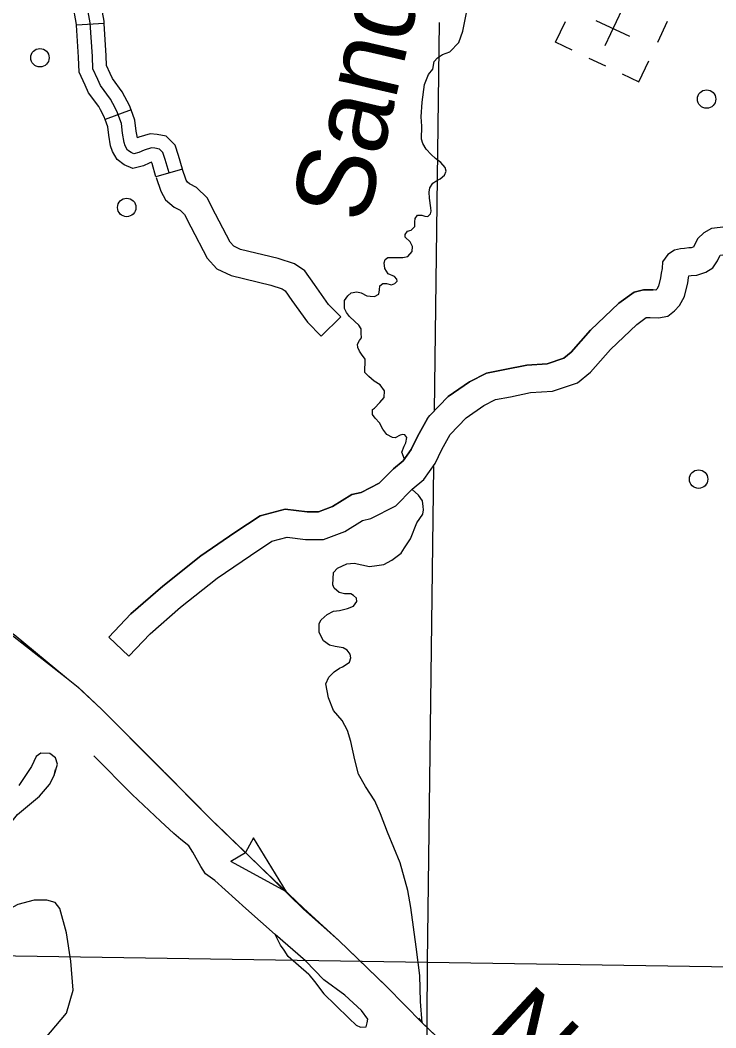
# Model space of a CAD drawing. Extents: x 1369979 to 1371646, y 379997 to 381064.
# Drawn here: x 1370948.5 to 1370992.7, y 380350.9 to 380415 of the extents above; entities that cross this region are included whole.
import ezdxf

# ---------------------------------------------------------------- set-up
doc = ezdxf.new("R2010")
doc.units = 0
doc.layers.add('R_Border Notes', color=7, linetype='Continuous')

msp = doc.modelspace()

# ---------------------------------------------------------------- linework, layer by layer
at = {"layer": 'R_Border Notes'}
for p, q in [((1370985.675, 380413.417), (1370987.683, 380417.652)), ((1370987.236, 380413.974), (1370985.108, 380414.982)), ((1370989.017, 380413.627), (1370989.644, 380414.951)), ((1370953.816, 380414.816), (1370952.061, 380414.709)), ((1370984.637, 380412.612), (1370985.696, 380412.11)), ((1370955.522, 380409.314), (1370953.875, 380408.7)), ((1370958.787, 380405.545), (1370957.096, 380405.067)), ((1370988.514, 380396.121), (1370988.535, 380396.122)), ((1370974.38, 380389.699), (1370974.518, 380389.882)), ((1370963.322, 380363.035), (1370962.804, 380362.099)), ((1370965.404, 380359.597), (1370963.315, 380363.034)), ((1370961.878, 380361.536), (1370962.795, 380362.088)), ((1370965.404, 380359.597), (1370961.877, 380361.529)), ((1370974.037, 380351.265), (1370978.237, 380347.272))]:
    msp.add_line(p, q, dxfattribs=at)
for points in [[(1370952.061, 380414.709), (1370952.059, 380414.749), (1370951.819, 380416.055), (1370951.819, 380417.029), (1370951.903, 380417.259), (1370952.08, 380417.772), (1370952.493, 380418.278), (1370953.065, 380418.69), (1370954.03, 380419.193), (1370954.825, 380419.643), (1370954.855, 380419.675), (1370954.867, 380419.705)], [(1370953.816, 380414.816), (1370953.807, 380414.962), (1370953.577, 380416.215), (1370953.577, 380416.722), (1370953.639, 380416.903), (1370953.707, 380416.986), (1370953.99, 380417.189), (1370954.87, 380417.649), (1370955.92, 380418.243), (1370956.371, 380418.719), (1370956.507, 380419.074)], [(1370954.362, 380409.725), (1370954.211, 380409.999), (1370953.585, 380410.86), (1370953.402, 380411.252), (1370953.089, 380411.931), (1370953.063, 380412.714), (1370952.933, 380414.856), (1370952.698, 380416.135), (1370952.698, 380416.874), (1370952.731, 380416.966)], [(1370973.965, 380408.871), (1370974.038, 380409.818), (1370974.189, 380410.94), (1370974.447, 380411.576), (1370974.719, 380411.91), (1370974.81, 380412.395), (1370975.007, 380412.622), (1370975.325, 380412.834), (1370975.795, 380413.016), (1370976.37, 380413.607), (1370976.627, 380414.32), (1370976.93, 380415.805)], [(1370975.118, 380414.871), (1370974.807, 380390.178)], [(1370983.584, 380413.111), (1370982.525, 380413.613), (1370983.153, 380414.937)], [(1370953.875, 380408.7), (1370953.809, 380408.878), (1370953.586, 380409.312), (1370953.468, 380409.526), (1370952.824, 380410.412), (1370952.605, 380410.882), (1370952.217, 380411.724), (1370952.185, 380412.673), (1370952.061, 380414.709)], [(1370955.522, 380409.314), (1370955.42, 380409.589), (1370955.138, 380410.138), (1370954.954, 380410.471), (1370954.346, 380411.309), (1370954.2, 380411.622), (1370953.962, 380412.138), (1370953.941, 380412.756), (1370953.816, 380414.816)], [(1370986.761, 380411.605), (1370987.82, 380411.103), (1370988.447, 380412.426)], [(1370957.941, 380405.306), (1370957.701, 380406.157), (1370957.554, 380406.598), (1370957.327, 380406.826), (1370957.046, 380406.879), (1370956.819, 380406.906), (1370956.351, 380406.759), (1370956.017, 380406.598), (1370955.71, 380406.518), (1370955.523, 380406.598), (1370955.309, 380406.759), (1370955.149, 380407.026), (1370955.082, 380407.24), (1370954.988, 380407.829), (1370954.908, 380408.444), (1370954.614, 380409.233), (1370954.362, 380409.725)], [(1370958.787, 380405.545), (1370958.541, 380406.415), (1370958.322, 380407.073), (1370957.757, 380407.638), (1370957.18, 380407.748), (1370956.735, 380407.801), (1370956.027, 380407.578), (1370955.926, 380407.53), (1370955.858, 380407.955), (1370955.767, 380408.657), (1370955.522, 380409.314)], [(1370957.096, 380405.067), (1370956.861, 380405.899), (1370956.831, 380405.988), (1370956.675, 380405.939), (1370956.321, 380405.769), (1370955.64, 380405.592), (1370955.079, 380405.832), (1370954.644, 380406.159), (1370954.341, 380406.664), (1370954.224, 380407.039), (1370954.118, 380407.703), (1370954.05, 380408.231), (1370953.875, 380408.7)], [(1370974.586, 380403.091), (1370974.511, 380403.702), (1370974.48, 380404.081), (1370974.526, 380404.369), (1370974.723, 380404.657), (1370974.904, 380404.778), (1370975.177, 380404.93), (1370975.449, 380405.172), (1370975.555, 380405.43), (1370975.51, 380405.657), (1370975.222, 380405.961), (1370974.889, 380406.218), (1370974.617, 380406.476), (1370974.283, 380406.825), (1370974.071, 380407.173), (1370973.996, 380407.446), (1370974.026, 380408.28), (1370973.965, 380408.871)], [(1370967.624, 380394.919), (1370968.868, 380396.161), (1370968.086, 380396.943), (1370967.189, 380398.216), (1370966.576, 380399.075), (1370965.925, 380399.522), (1370964.886, 380399.859), (1370962.485, 380400.447), (1370962.051, 380400.648), (1370961.826, 380400.901), (1370960.886, 380402.683), (1370960.356, 380403.715), (1370959.688, 380404.383), (1370959.238, 380404.609), (1370959.106, 380404.72), (1370959.034, 380404.854), (1370958.77, 380405.6)], [(1370957.113, 380405.013), (1370957.422, 380404.14), (1370957.716, 380403.594), (1370958.262, 380403.131), (1370958.646, 380402.939), (1370958.918, 380402.667), (1370959.327, 380401.871), (1370960.37, 380399.893), (1370960.98, 380399.206), (1370961.902, 380398.78), (1370964.405, 380398.167), (1370965.14, 380397.929), (1370965.324, 380397.802), (1370965.755, 380397.199), (1370966.736, 380395.808), (1370967.624, 380394.919)], [(1370969.42, 380396.173), (1370969.226, 380396.437), (1370969.105, 380396.68), (1370969.089, 380396.953), (1370969.105, 380397.195), (1370969.317, 380397.498), (1370969.529, 380397.68), (1370969.877, 380397.756), (1370970.165, 380397.68), (1370970.513, 380397.498), (1370970.74, 380397.468), (1370970.997, 380397.453), (1370971.285, 380397.604), (1370971.331, 380397.877), (1370971.346, 380398.12), (1370971.527, 380398.286), (1370971.77, 380398.286), (1370972.088, 380398.195), (1370972.3, 380398.271), (1370972.451, 380398.423), (1370972.436, 380398.544), (1370972.269, 380398.726), (1370971.876, 380398.893), (1370971.664, 380399.226), (1370971.618, 380399.59), (1370971.694, 380399.802), (1370971.861, 380399.923), (1370972.239, 380399.939), (1370972.799, 380399.923), (1370973.133, 380399.984), (1370973.405, 380400.317), (1370973.42, 380400.621), (1370973.269, 380400.924), (1370972.966, 380401.227), (1370972.951, 380401.394), (1370973.102, 380401.606), (1370973.329, 380401.666), (1370973.572, 380401.909), (1370973.572, 380402.197), (1370973.602, 380402.409), (1370973.738, 380402.621), (1370974.026, 380402.621), (1370974.208, 380402.561), (1370974.405, 380402.546), (1370974.571, 380402.697), (1370974.617, 380402.879), (1370974.586, 380403.091)], [(1370993.355, 380401.889), (1370992.428, 380401.769), (1370991.947, 380401.502), (1370991.565, 380401.147), (1370991.401, 380400.817), (1370991.291, 380400.598), (1370991.284, 380400.588), (1370991.204, 380400.564), (1370991.155, 380400.546), (1370990.991, 380400.538), (1370990.731, 380400.508), (1370990.476, 380400.476), (1370990.088, 380400.392), (1370989.669, 380400.113), (1370989.321, 380399.665), (1370989.295, 380399.229), (1370989.235, 380398.939), (1370989.197, 380398.647), (1370989.064, 380398.105), (1370988.956, 380397.915), (1370988.907, 380397.86), (1370988.728, 380397.871)], [(1370988.535, 380396.122), (1370989.062, 380396.089), (1370989.662, 380396.204), (1370990.08, 380396.533), (1370990.393, 380396.887), (1370990.713, 380397.447), (1370990.927, 380398.323), (1370990.969, 380398.646), (1370990.995, 380398.769), (1370991.138, 380398.785), (1370991.508, 380398.804), (1370991.753, 380398.893), (1370992.075, 380398.988), (1370992.523, 380399.276), (1370992.815, 380399.715), (1370992.973, 380400.031), (1370992.992, 380400.07), (1370993.504, 380400.136), (1370994.074, 380400.159), (1370994.375, 380400.131), (1370995.218, 380399.916), (1370996.456, 380399.805)], [(1370988.535, 380396.122), (1370989.062, 380396.089), (1370989.662, 380396.204), (1370990.08, 380396.533), (1370990.393, 380396.887), (1370990.713, 380397.447), (1370990.927, 380398.323), (1370990.969, 380398.646), (1370990.995, 380398.769), (1370991.138, 380398.785), (1370991.508, 380398.804), (1370991.753, 380398.893), (1370992.075, 380398.988), (1370992.523, 380399.276), (1370992.815, 380399.715), (1370992.973, 380400.031), (1370992.992, 380400.07), (1370993.504, 380400.136), (1370994.074, 380400.159), (1370994.375, 380400.131), (1370995.218, 380399.916), (1370996.456, 380399.805)], [(1370974.518, 380389.882), (1370975.698, 380391.092), (1370977.048, 380392.032), (1370978.119, 380392.568), (1370979.304, 380392.805), (1370980.699, 380393.084), (1370981.978, 380393.161), (1370983.047, 380393.525), (1370983.512, 380393.913), (1370984.749, 380395.309), (1370986.555, 380397.034), (1370987.516, 380397.73), (1370988.107, 380397.878), (1370988.728, 380397.871)], [(1370988.728, 380397.871), (1370988.107, 380397.878), (1370987.516, 380397.73), (1370986.555, 380397.034), (1370984.749, 380395.309), (1370983.512, 380393.913), (1370983.047, 380393.525), (1370981.978, 380393.161), (1370980.699, 380393.084), (1370979.304, 380392.805), (1370978.119, 380392.568), (1370977.048, 380392.032), (1370975.698, 380391.092), (1370974.518, 380389.882)], [(1370970.888, 380390.271), (1370971.01, 380390.353), (1370971.343, 380390.717), (1370971.615, 380391.035), (1370971.646, 380391.46), (1370971.373, 380391.838), (1370970.994, 380392.066), (1370970.994, 380392.066), (1370970.646, 380392.354), (1370970.389, 380392.627), (1370970.389, 380392.884), (1370970.419, 380393.172), (1370970.419, 380393.475), (1370970.177, 380393.794), (1370970.056, 380393.976), (1370969.95, 380394.203), (1370969.934, 380394.415), (1370970.056, 380394.643), (1370970.177, 380394.824), (1370970.162, 380395.128), (1370970.162, 380395.385), (1370970.01, 380395.628), (1370969.753, 380395.855), (1370969.42, 380396.173)], [(1370975.815, 380388.678), (1370976.84, 380389.745), (1370977.949, 380390.517), (1370978.695, 380390.891), (1370979.649, 380391.081), (1370980.926, 380391.337), (1370982.32, 380391.421), (1370983.922, 380391.966), (1370984.74, 380392.648), (1370986.016, 380394.088), (1370987.683, 380395.68), (1370988.273, 380396.108), (1370988.323, 380396.12), (1370988.51, 380396.12), (1370988.514, 380396.121)], [(1370975.815, 380388.678), (1370976.84, 380389.745), (1370977.949, 380390.517), (1370978.695, 380390.891), (1370979.649, 380391.081), (1370980.926, 380391.337), (1370982.32, 380391.421), (1370983.922, 380391.966), (1370984.74, 380392.648), (1370986.016, 380394.088), (1370987.683, 380395.68), (1370988.273, 380396.108), (1370988.323, 380396.12), (1370988.51, 380396.12), (1370988.514, 380396.121)], [(1370972.906, 380387.107), (1370972.736, 380387.543), (1370972.902, 380387.937), (1370972.993, 380388.149), (1370973.054, 380388.483), (1370972.933, 380388.649), (1370972.796, 380388.68), (1370972.63, 380388.634), (1370972.327, 380388.467), (1370972.16, 380388.483), (1370971.797, 380388.665), (1370971.54, 380389.013), (1370971.328, 380389.422), (1370971.04, 380389.71), (1370970.888, 380389.953), (1370970.888, 380390.271)], [(1370955.382, 380374.574), (1370954.105, 380375.782), (1370955.517, 380377.275), (1370957.547, 380379.04), (1370959.961, 380380.952), (1370962.13, 380382.435), (1370963.742, 380383.511), (1370965.325, 380383.931), (1370966.719, 380383.76), (1370967.446, 380383.76), (1370968.336, 380384.092), (1370969.561, 380384.855), (1370970.169, 380384.993), (1370971.307, 380385.585), (1370972.223, 380386.489), (1370972.839, 380387.011), (1370973.334, 380387.722), (1370973.733, 380388.545), (1370974.38, 380389.699)], [(1370974.38, 380389.699), (1370973.733, 380388.545), (1370973.334, 380387.722), (1370972.839, 380387.011), (1370972.223, 380386.489), (1370971.307, 380385.585), (1370970.169, 380384.993), (1370969.561, 380384.855), (1370968.336, 380384.092), (1370967.446, 380383.76), (1370966.719, 380383.76), (1370965.325, 380383.931), (1370963.742, 380383.511), (1370962.13, 380382.435), (1370959.961, 380380.952), (1370957.547, 380379.04), (1370955.517, 380377.275), (1370954.105, 380375.782), (1370955.382, 380374.574)], [(1370955.382, 380374.574), (1370956.735, 380376.005), (1370958.67, 380377.687), (1370961.004, 380379.536), (1370963.114, 380380.978), (1370964.475, 380381.887), (1370965.448, 380382.145), (1370966.611, 380382.002), (1370967.763, 380382.002), (1370969.116, 380382.506), (1370970.239, 380383.206), (1370970.779, 380383.329), (1370972.353, 380384.147), (1370973.41, 380385.191), (1370974.15, 380385.818), (1370974.856, 380386.831), (1370975.291, 380387.731), (1370975.815, 380388.678)], [(1370974.762, 380386.638), (1370974.365, 380355.122)], [(1370972.918, 380381.459), (1370973.296, 380382.041), (1370973.705, 380383.056), (1370974.083, 380383.617), (1370974.129, 380383.89), (1370974.099, 380384.102), (1370974.068, 380384.466), (1370973.796, 380384.815), (1370973.4, 380385.182)], [(1370967.481, 380376.088), (1370967.496, 380376.654), (1370967.618, 380376.896), (1370967.996, 380377.23), (1370968.39, 380377.442), (1370968.784, 380377.488), (1370969.283, 380377.609), (1370969.662, 380377.76), (1370969.889, 380378.048), (1370969.859, 380378.276), (1370969.677, 380378.442), (1370969.495, 380378.533), (1370969.102, 380378.549), (1370968.753, 380378.624), (1370968.45, 380378.897), (1370968.36, 380379.125), (1370968.405, 380379.898), (1370968.647, 380380.17), (1370969.238, 380380.443), (1370969.707, 380380.504), (1370970.207, 380380.383), (1370970.692, 380380.292), (1370971.161, 380380.337), (1370971.6, 380380.413), (1370972.1, 380380.686), (1370972.706, 380381.14), (1370972.918, 380381.459)], [(1370939.818, 380380.473), (1370942.863, 380378.905), (1370946.795, 380376.745), (1370948.087, 380375.958), (1370951.427, 380373.206), (1370952.048, 380372.703)], [(1370947.304, 380376.434), (1370951.427, 380373.206), (1370952.048, 380372.703), (1370952.154, 380372.605)], [(1370969.753, 380367.99), (1370969.495, 380369.146), (1370969.298, 380369.859), (1370968.95, 380370.48), (1370968.39, 380371.117), (1370968.072, 380371.92), (1370967.905, 380372.83), (1370968.102, 380373.239), (1370968.45, 380373.588), (1370968.784, 380373.815), (1370968.98, 380373.906), (1370969.147, 380374.012), (1370969.42, 380374.194), (1370969.495, 380374.467), (1370969.465, 380374.709), (1370969.268, 380374.967), (1370969.011, 380375.118), (1370968.496, 380375.194), (1370968.148, 380375.27), (1370967.754, 380375.558), (1370967.481, 380376.088)], [(1370948.522, 380375.481), (1370951.427, 380373.206), (1370952.048, 380372.703), (1370952.154, 380372.605), (1370952.159, 380372.599)], [(1370952.048, 380372.703), (1370953.674, 380371.194), (1370960.74, 380364.077), (1370963.719, 380361.207), (1370966.498, 380358.485), (1370968.745, 380356.502), (1370971.79, 380353.543), (1370974.037, 380351.265)], [(1370952.154, 380372.605), (1370953.674, 380371.194), (1370956.572, 380368.275)], [(1370953.293, 380371.547), (1370953.674, 380371.194), (1370956.572, 380368.275), (1370956.578, 380368.269)], [(1370950.632, 380367.002), (1370950.85, 380367.715), (1370950.729, 380368.109), (1370950.366, 380368.382), (1370949.79, 380368.412), (1370949.488, 380368.2), (1370949.185, 380367.563), (1370948.397, 380366.351)], [(1370955.587, 380365.794), (1370953.149, 380368.245)], [(1370956.572, 380368.275), (1370960.74, 380364.077), (1370960.936, 380363.888)], [(1370973.13, 380359.681), (1370972.63, 380361.442), (1370971.842, 380363.382), (1370971.388, 380364.564), (1370971.025, 380365.383), (1370970.434, 380366.292), (1370969.995, 380367.08), (1370969.753, 380367.99)], [(1370950.996, 380358.526), (1370950.693, 380358.908), (1370950.178, 380359.06), (1370949.36, 380359.06), (1370948.331, 380358.787), (1370946.877, 380358.029), (1370945.514, 380356.999), (1370944.848, 380356.695), (1370944.303, 380356.726), (1370944, 380357.029), (1370943.939, 380357.726), (1370944.151, 380358.817), (1370944.848, 380359.727), (1370946.18, 380361.879), (1370948.3, 380364.517), (1370949.694, 380365.668), (1370950.33, 380366.426), (1370950.632, 380367.002), (1370950.723, 380367.366)], [(1370957.667, 380367.172), (1370960.74, 380364.077), (1370960.936, 380363.888), (1370960.941, 380363.883)], [(1370960.853, 380360.313), (1370960.266, 380360.731), (1370959.963, 380361.201), (1370959.463, 380362.11), (1370959.191, 380362.52), (1370958.691, 380362.929), (1370958.252, 380363.308), (1370957.404, 380364.096), (1370955.587, 380365.794)], [(1370960.936, 380363.888), (1370963.719, 380361.207), (1370966.502, 380358.547)], [(1370962.056, 380362.81), (1370963.719, 380361.207), (1370965.404, 380359.597)], [(1370964.7, 380356.872), (1370962.822, 380358.524), (1370960.853, 380360.313)], [(1370974.037, 380351.265), (1370973.932, 380352.617), (1370973.887, 380354.27), (1370973.66, 380356.104), (1370973.326, 380358.589), (1370973.13, 380359.681)], [(1370950.057, 380350.26), (1370951.42, 380351.887), (1370951.844, 380353.343), (1370951.692, 380355.192), (1370951.42, 380356.98), (1370950.996, 380358.526)], [(1370966.502, 380358.547), (1370968.223, 380356.963)], [(1370966.523, 380358.528), (1370968.223, 380356.963), (1370968.23, 380356.957)], [(1370966.835, 380354.332), (1370967.198, 380353.892), (1370967.774, 380353.104), (1370968.531, 380352.392), (1370969.394, 380351.543), (1370969.833, 380351.118), (1370970.121, 380350.982), (1370970.469, 380351.012), (1370970.545, 380351.255), (1370970.575, 380351.497), (1370970.181, 380352.043), (1370969.121, 380353.013), (1370967.774, 380353.998), (1370966.623, 380355.196), (1370964.7, 380356.872)], [(1370966.835, 380354.332), (1370965.517, 380355.484), (1370965.26, 380355.887), (1370965.033, 380356.205), (1370964.7, 380356.872)], [(1370968.223, 380356.963), (1370968.745, 380356.502), (1370969.909, 380355.371)], [(1370968.23, 380356.957), (1370968.745, 380356.502), (1370969.909, 380355.371), (1370969.916, 380355.364)], [(1370917.867, 380355.995), (1370974.365, 380355.122)], [(1370969.909, 380355.371), (1370971.79, 380353.543), (1370974.037, 380351.266)], [(1370974.365, 380355.122), (1370974.185, 380325.167)], [(1370974.365, 380355.122), (1371011.907, 380354.547)], [(1370971.026, 380354.286), (1370971.79, 380353.543), (1370974.037, 380351.266), (1370974.037, 380351.265), (1370974.308, 380351.007)], [(1370973.8, 380351.561), (1370974.037, 380351.265), (1370979.057, 380346.492)]]:
    msp.add_lwpolyline(points, dxfattribs=at)
for centre in [(1370949.729, 380412.632), (1370992.124, 380410.002), (1370955.248, 380403.111), (1370991.616, 380385.836)]:
    msp.add_circle(centre, 0.586, dxfattribs=at)

# ---------------------------------------------------------------- texts
for s, rotation, p in [('Sandy', 76.91986, (1370970.488, 380401.979)), ('North', 316.97596, (1370977.521, 380350.296))]:
    msp.add_text(s, height=4.95, rotation=rotation, dxfattribs=at).set_placement(p)

doc.saveas('drawing.dxf')
